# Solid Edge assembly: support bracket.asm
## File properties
Author: Deepak Maini
Template: normal.asm
Last saved by: Robert a Rhodes jr
Revision: 2
Application: Solid Edge
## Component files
adjusting_nut_handle.par
adjusting_screw_guide.par
Stock_support_base.par
thrust_bearing.par
adjusting_screw_nut.par
support_adjusting_screw.par
support_roller_bracket.par
stock_support_roller.par
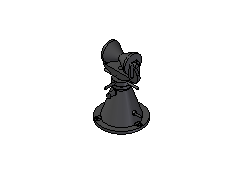
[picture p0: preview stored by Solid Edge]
